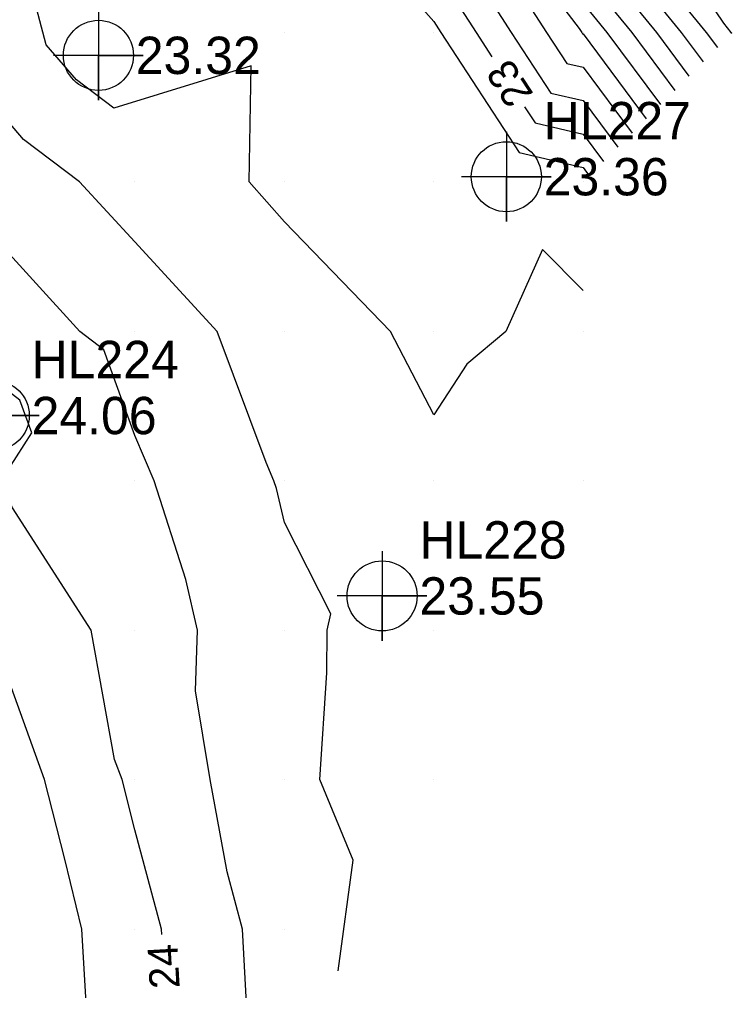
# Model space of a CAD drawing. Extents: x 2531902 to 2533249, y 715219 to 716099.
# Drawn here: x 2532832.3 to 2532880, y 715345.9 to 715410.9 of the extents above; entities that cross this region are included whole.
import ezdxf

# ---------------------------------------------------------------- set-up
doc = ezdxf.new("R2010")
doc.units = 0
for name, color, linetype in [('DTM Contours Major', 7, 'Continuous'), ('DTM Contours Major Text', 7, 'Continuous'), ('DTM Contours Minor', 7, 'Continuous'), ('Exist DTM QL2 LIDAR Elevation Point', 7, 'Continuous'), ('Exist DTM Regular Point CELL', 7, 'Continuous'), ('Exist DTM Regular Point Cogo Elevation', 7, 'Continuous'), ('Exist DTM Regular Point Cogo Number', 7, 'Continuous')]:
    doc.layers.add(name, color=color, linetype=linetype)

msp = doc.modelspace()

# ---------------------------------------------------------------- linework, layer by layer
at = {"layer": 'DTM Contours Major'}
for points in [[(2532839.861, 715456.223), (2532838.944, 715455.625), (2532835.265, 715452.415), (2532835.146, 715449.522), (2532835.222, 715446.553), (2532838.364, 715445.902), (2532844.179, 715444.179), (2532846.736, 715440), (2532850, 715438.063), (2532852.744, 715435.576), (2532859.134, 715432.122), (2532860, 715433.238), (2532862.822, 715430), (2532863.338, 715426.662), (2532865.381, 715420), (2532870, 715413.971), (2532873.251, 715410), (2532876.127, 715406.127)], [(2532830, 715436.589), (2532838.988, 715430), (2532841.423, 715425.073), (2532841.577, 715424.802), (2532841.786, 715424.812), (2532842.049, 715424.764), (2532842.081, 715425.065), (2532840.97, 715430), (2532845.757, 715434.243), (2532850, 715431.725), (2532850.587, 715431.193), (2532852.793, 715430), (2532854.699, 715425.301), (2532855.034, 715420), (2532860, 715414.389), (2532862.831, 715410), (2532863.897, 715408.365)], [(2532841.803, 715349.636), (2532841.784, 715350), (2532840, 715356.638), (2532839.135, 715360), (2532838.644, 715361.356), (2532837.071, 715370), (2532831.814, 715378.186), (2532831.041, 715380), (2532833.095, 715383.202), (2532832.301, 715385.392), (2532830.321, 715386.918), (2532824.913, 715390), (2532820, 715395.286), (2532816.271, 715400), (2532811.177, 715403.719), (2532810, 715405.622), (2532802.725, 715410), (2532799.994, 715410.449), (2532795.245, 715408.971), (2532789.788, 715405.868), (2532786.068, 715398.536)], [(2532866.082, 715405.014), (2532866.777, 715403.949), (2532870, 715403.202), (2532871.364, 715401.364)]]:
    msp.add_lwpolyline(points, dxfattribs=at)
at = {"layer": 'DTM Contours Minor'}
for points in [[(2532830, 715469.839), (2532837.687, 715460), (2532832.9, 715455.822), (2532832.65, 715449.754), (2532832.809, 715443.526), (2532839.401, 715442.16), (2532841.529, 715441.529), (2532842.465, 715440), (2532850, 715435.527), (2532851.881, 715433.822), (2532858.953, 715430), (2532860, 715427.418), (2532862.275, 715420), (2532869.728, 715410.272), (2532869.903, 715410), (2532869.957, 715409.918), (2532870, 715409.908), (2532874.222, 715404.222)], [(2532831.603, 715442.012), (2532839.92, 715440.288), (2532840.204, 715440.204), (2532840.329, 715440), (2532850, 715434.26), (2532851.45, 715432.946), (2532856.9, 715430), (2532860, 715422.355), (2532860.722, 715420), (2532863.088, 715416.912), (2532867.546, 715410), (2532868.897, 715407.929), (2532870, 715407.673), (2532873.269, 715403.269)], [(2532830.396, 715440.498), (2532832.798, 715440), (2532840, 715435.024), (2532842.638, 715437.362), (2532850, 715432.992), (2532851.018, 715432.069), (2532854.847, 715430), (2532858.153, 715421.847), (2532858.27, 715420), (2532860, 715418.045), (2532865.188, 715410), (2532867.837, 715405.939), (2532870, 715405.438), (2532872.317, 715402.317)], [(2532832.057, 715430), (2532832.614, 715428.873), (2532836.2, 715422.572), (2532841.047, 715422.823), (2532847.159, 715421.702), (2532847.902, 715428.693), (2532847.607, 715430), (2532848.876, 715431.124), (2532850, 715430.457), (2532850.155, 715430.316), (2532850.74, 715430), (2532851.245, 715428.755), (2532851.799, 715420), (2532860, 715410.734), (2532860.473, 715410), (2532865.717, 715401.96), (2532870, 715400.967), (2532870.412, 715400.412)], [(2532870, 715392.728), (2532867.284, 715395.467), (2532864.831, 715390), (2532862.208, 715387.792), (2532860, 715384.416), (2532857.096, 715390), (2532850, 715397.319), (2532847.644, 715400), (2532847.776, 715407.776), (2532838.579, 715404.928), (2532836.087, 715406.82), (2532834.057, 715409.178), (2532832.037, 715416.892), (2532838.774, 715414.209), (2532847.17, 715412.83), (2532844.853, 715420), (2532840.309, 715420.833), (2532830.823, 715420.341)], [(2532870.238, 715419.762), (2532878.23, 715410), (2532878.984, 715408.984)], [(2532873.076, 715420), (2532879.388, 715410.612), (2532879.889, 715410), (2532879.936, 715409.936)], [(2532870, 715418.026), (2532876.57, 715410), (2532878.031, 715408.031)], [(2532870, 715415.998), (2532874.91, 715410), (2532877.079, 715407.079)], [(2532870, 715411.944), (2532871.591, 715410), (2532875.174, 715405.174)], [(2532853.598, 715347.197), (2532854.611, 715354.611), (2532852.382, 715360), (2532852.85, 715367.15), (2532852.856, 715370), (2532853.104, 715371.088), (2532850, 715377.217), (2532849.472, 715379.472), (2532849.303, 715380), (2532848.788, 715381.212), (2532845.511, 715390), (2532840, 715395.991), (2532836.294, 715400), (2532832.542, 715402.848), (2532830, 715405.801)], [(2532845.604, 715324.798), (2532844.587, 715329.174), (2532845.378, 715335.378), (2532847.444, 715339.106), (2532847.744, 715339.969), (2532847.713, 715340.503), (2532847.205, 715350), (2532846.177, 715353.823), (2532845.031, 715360), (2532844.049, 715365.951), (2532844.197, 715370), (2532843.4, 715373.4), (2532841.288, 715380), (2532840, 715383.033), (2532837.924, 715388.758), (2532836.311, 715390), (2532830, 715396.906)], [(2532830, 715314.108), (2532832.558, 715320), (2532834.293, 715325.707), (2532834.699, 715330), (2532835.448, 715334.552), (2532837.203, 715340), (2532836.84, 715343.16), (2532836.441, 715350), (2532835.312, 715354.688), (2532833.945, 715360), (2532830.507, 715369.493)]]:
    msp.add_lwpolyline(points, dxfattribs=at)
at = {"layer": 'Exist DTM QL2 LIDAR Elevation Point'}
for p, q in [((2532850, 715410), (2532850, 715410)), ((2532860, 715410), (2532860, 715410)), ((2532870, 715410), (2532870, 715410)), ((2532880, 715410), (2532880, 715410)), ((2532840, 715400), (2532840, 715400)), ((2532850, 715400), (2532850, 715400)), ((2532860, 715400), (2532860, 715400)), ((2532870, 715400), (2532870, 715400)), ((2532840, 715390), (2532840, 715390)), ((2532850, 715390), (2532850, 715390)), ((2532860, 715390), (2532860, 715390)), ((2532870, 715390), (2532870, 715390)), ((2532840, 715380), (2532840, 715380)), ((2532850, 715380), (2532850, 715380)), ((2532860, 715380), (2532860, 715380)), ((2532870, 715380), (2532870, 715380)), ((2532840, 715370), (2532840, 715370)), ((2532850, 715370), (2532850, 715370)), ((2532860, 715370), (2532860, 715370)), ((2532840, 715360), (2532840, 715360)), ((2532850, 715360), (2532850, 715360)), ((2532860, 715360), (2532860, 715360)), ((2532840, 715350), (2532840, 715350)), ((2532850, 715350), (2532850, 715350))]:
    msp.add_line(p, q, dxfattribs=at)
at = {"layer": 'Exist DTM Regular Point CELL'}
for points in [[(2532837.558, 715411.468), (2532837.558, 715405.468), (2532837.558, 715408.468), (2532840.558, 715408.468), (2532834.558, 715408.468)], [(2532864.859, 715403.348), (2532864.859, 715397.348), (2532864.859, 715400.348), (2532867.859, 715400.348), (2532861.859, 715400.348)], [(2532830.586, 715387.366), (2532830.586, 715381.366), (2532830.586, 715384.366), (2532833.586, 715384.366), (2532827.586, 715384.366)], [(2532856.543, 715375.293), (2532856.543, 715369.293), (2532856.543, 715372.293), (2532859.543, 715372.293), (2532853.543, 715372.293)]]:
    msp.add_lwpolyline(points, dxfattribs=at)
for centre in [(2532837.558, 715408.468), (2532864.859, 715400.348), (2532830.586, 715384.366), (2532856.543, 715372.293)]:
    msp.add_circle(centre, 2.344, dxfattribs=at)

# ---------------------------------------------------------------- texts
at = {"layer": 'DTM Contours Major Text'}
for s, rotation, p in [('23', 123.11413, (2532866.718, 715405.871)), ('24', 93.22601, (2532843, 715346.068))]:
    msp.add_text(s, height=2, rotation=rotation, dxfattribs=at).set_placement(p)
at = {"layer": 'Exist DTM Regular Point Cogo Elevation'}
for s, p in [('23.32', (2532840.058, 715407.218)), ('23.36', (2532867.359, 715399.098)), ('24.06', (2532833.086, 715383.116)), ('23.55', (2532859.043, 715371.043))]:
    msp.add_text(s, height=2.5, dxfattribs=at).set_placement(p)
at = {"layer": 'Exist DTM Regular Point Cogo Number'}
for s, p in [('HL227', (2532867.359, 715402.848)), ('HL224', (2532833.086, 715386.866)), ('HL228', (2532859.043, 715374.793))]:
    msp.add_text(s, height=2.5, dxfattribs=at).set_placement(p)

doc.saveas('drawing.dxf')
